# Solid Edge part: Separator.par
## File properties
Author: morva
Template: iso metric part.par
Last saved by: morva
Revision: 14
Application: Solid Edge
Density: 2712.000 kg/m^3
Accuracy: 0.990
Username: morva
Material: Aluminum, 6061-T6
Face Style: Aluminum
Fill Style: ANSI38(Aluminum)
Virtual Style: Polished aluminum
Grouping: Metals\Aluminium Alloys
LibraryName: Materials
Coef. of Thermal Exp: 2.3e-05
Thermal Conductivity: 180.0
Specific Heat: 920.0
Modulus of Elasticity: 68947570000.0
Poisson's Ratio: 0.33
Yield Stress: 275790280.0
Ultimate Stress: 310264065.0
Elongation: 0.0
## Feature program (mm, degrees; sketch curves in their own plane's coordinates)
sketch for "unnamed Protrusion 1" plane through (0, 0, 0) normal (0, 0, 1) x-axis (1, 0, 0)
  line (-45, 5) -> (-45, -5)
  line (-45, -5) -> (45, -5)
  line (45, -5) -> (45, 5)
  line (45, 5) -> (-45, 5)
  dimension (linear) = 45
  dimension (linear) = 45
extrude "unnamed Protrusion 1" add finite 45 along +normal
sketch for "ExtrudedCutout_1" plane through (0, 0, 0) normal (0, 0, -1) x-axis (1, 0, 0)
  line (-39, -5) -> (-39, 5)
  line (-39, 5) -> (-19, 5)
  line (-19, 5) -> (-19, -5)
  line (-19, -5) -> (-39, -5)
  dimension (linear) = 19
  dimension (linear) = 39
extrude "ExtrudedCutout_1" cut finite 20 along -normal
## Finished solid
Body 1: solid body, 10 faces, 24 edges, 16 vertices.
  Faces by surface: plane 10
  Edges by curve: line 24
Bounding box of the edges (mm): 90.000 x 10.000 x 45.000, from (-45, -5, 0) to (45, 5, 45).
Planar faces by outward normal: +x 2, +y 1, +z 1, -x 2, -y 1, -z 3
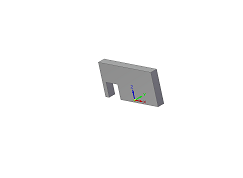
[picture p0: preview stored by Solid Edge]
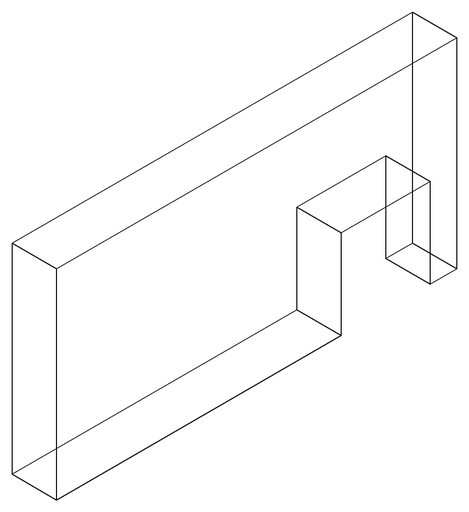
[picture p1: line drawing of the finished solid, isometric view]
